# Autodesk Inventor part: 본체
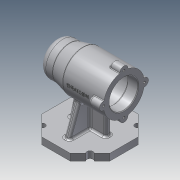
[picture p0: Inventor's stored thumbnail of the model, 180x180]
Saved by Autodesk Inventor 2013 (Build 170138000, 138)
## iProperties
Created: 2021-01
Part Number: 본체
Material: 알루미늄 6061
Document SubType Name: Modeling
Designer: user
Density: 2.71 g/cm^3
Mass: 632.297 g
Surface Area: 613.777 cm^2
Volume: 233.32 cm^3
Author: user
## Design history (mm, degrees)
sketch "스케치1"
  geometry: L1 (0, 0)-(-100, 0); L2 (-100, 0)-(-100, 25); L3 (0, 30)-(0, 0); L4 (0, 30)-(-60, 30); L5 (-60, 30)-(-80, 25); L6 (-80, 25)-(-100, 25); L7 (0, 21)-(-15, 21); L8 (-15, 21)-(-15, 24); L9 (-15, 24)-(-57, 24); L10 (-57, 24)-(-57, 21); L11 (-57, 21)-(-69, 21); L12 (-69, 21)-(-69, 17.5); L13 (-69, 17.5)-(-87, 17.5); L14 (-87, 17.5)-(-87, 16); L15 (-87, 16)-(-91, 16); L16 (-91, 16)-(-91, 10.5); L17 (-91, 10.5)-(-94, 10.5); L18 (-94, 10.5)-(-94, 0)
  constraints: 37 end point, 10 parallel, 5 perpendicular, 2 point on line, 1 collinear, 1 horizontal
  dimensions: "d1" = 60 diameter of L4 L1; "d3" = 48 diameter of L9 L1; "d4" = 42 diameter of L7 L1; "d5" = 15 distance between parallel lines of L3 L8; "d6" = 42 distance between parallel lines of L10 L8; "d7" = 12 distance between parallel lines of L10 L12; "d8" = 42 diameter of L11 L1; "d9" = 3 distance between parallel lines of L16 L18; "d10" = 4 distance between parallel lines of L14 L16; "d11" = 18 distance between parallel lines of L12 L14; "d12" = 100 distance of L1.start L1.end; "d13" = 40 distance from line of L2 L4.end; "d14" = 20 distance of L5.end L2.end; "d15" = 50 diameter of L6 L1; "d16" = 35 diameter of L13 L1; "d17" = 32 diameter of L15 L1; "d18" = 21 diameter of L17 L1
revolve "회전1" sketch "스케치1" stored, may be unused: angle "d19" = 90 deg
sketch "스케치2"
  geometry: C1 r 21 at (0, 0) reference; C2 r 6 at (0, 30); 1 further point
  constraints: 2 vertical alignment, 1 centre point, 1 other
  dimensions: "d20" = 12 diameter of C2
extrude "돌출1" join sketch "스케치2" distance "d22" = 16; taper "d23" = 0 deg
sketch "스케치3"
  geometry: A1 r 6 centre (0, 0) between (5.97, -0.6) and (-5.97, -0.6) reference; 1 further point
  constraints: 1 coincident
hole "구멍1" sketch "스케치3" at (0, 0) diameter "d24" = 3.242; stored, may be unused: countersink angle "d28" = 90 deg, drill point angle "d30" = 118 deg; dims "d25" = 8, "d26" = 4, "d27" = 2, "d29" = 10
node "작업 평면1"
sketch "스케치4"
  geometry: L1 (29.289, -50)-(0, -20.711); L2 (0, -20.711)-(0, 20.711); L3 (0, 20.711)-(29.289, 50); L4 (29.289, 50)-(70.711, 50); L5 (70.711, 50)-(100, 20.711); L6 (100, 20.711)-(100, -20.711); L7 (100, -20.711)-(70.711, -50); L8 (70.711, -50)-(29.289, -50); 3 further points
  constraints: 16 end point, 1 coincident, 1 horizontal alignment, 1 midpoint, 17 other
  dimensions: "d35" = 50 distance from line of L2 point (50, 0)
extrude "돌출2" join sketch "스케치4" distance "d36" = 10; taper "d37" = 0 deg
sketch "스케치5"
  geometry: L1 (-29.289, 50)-(-70.711, 50) reference; L2 (-70.711, 50)-(-100, 20.711) reference; L3 (-100, 20.711)-(-100, -20.711) reference; L4 (-70.711, -50)-(-29.289, -50) reference; L5 (-50, 50)-(-50, -50); L6 (-100, 0)-(0, 0); L7 (-50, 0)-(-85.355, 35.355); L8 (0, 20.711)-(-29.289, 50) reference; L9 (-100, -20.711)-(-70.711, -50) reference; L10 (-29.289, -50)-(0, -20.711) reference; C1 r 4.5 at (-85.355, 35.355); C2 r 4.5 at (-14.645, 35.355); C3 r 4.5 at (-14.645, -35.355); C4 r 4.5 at (-85.355, -35.355)
  constraints: 8 midpoint, 6 end point, 4 centre point, 2 perpendicular
  dimensions: "d38" = 9 diameter of C1; "d41" = 9 diameter of C2; "d42" = 9 diameter of C3; "d43" = 9 diameter of C4
extrude "돌출3" cut sketch "스케치5" stored distance "d39" = 10; taper "d40" = 0 deg
sketch "스케치6"
  geometry: L1 (0, -20.711)-(0, 20.711) reference; L2 (-100, 20.711)-(-100, -20.711) reference; L3 (-77, -4)-(-23, -4); L4 (-23, -4)-(-23, 4); L5 (-23, 4)-(-77, 4); L6 (-77, 4)-(-77, -4); L7 (-77, -4)-(-23, 4); L8 (-23, -4)-(-77, 4); 4 further points
  constraints: 12 end point, 4 midpoint, 2 parallel, 1 horizontal, 1 horizontal alignment, 1 perpendicular
  dimensions: "d44" = 8 distance of L3.end L4.end; "d46" = 50 distance from line of L1 point (-50, 0); "d47" = 23 distance between parallel lines of L2 L6
extrude "돌출4" join sketch "스케치6" stored distance "d48" = 10; taper "d49" = 0 deg
fillet "모깎기1" dims "d50" = 10
fillet "모깎기2" dims "d51" = 3
fillet "모깎기3" dims "d52" = 3
fillet "모깎기4" dims "d53" = 1
feature "면 기울기1" dims angle "d54" = 11 deg
node "작업 평면2"
sketch "스케치7"
  geometry: L1 (70.711, 0)-(-29.289, 0) reference; L2 (-29.289, 0)-(-29.289, 10) reference; L3 (-29.289, 10)-(16.711, 10) reference; L4 (16.711, 10)-(16.711, 45.268) reference; L5 (24.711, 45.268)-(24.711, 10) reference; L6 (24.711, 10)-(70.711, 10) reference; L7 (70.711, 10)-(70.711, 0) reference; L8 (1.104, 52.293)-(-14.289, 10); C1 r 24 at (20.711, 75) reference; A1 r 30 centre (20.711, 75) between (24.711, 45.268) and (16.711, 45.268) reference; 1 further point
  constraints: 2 end point, 1 point on circle, 1 point on line
  dimensions: "d56" = 15 distance from line of L8.end L2; "d57" = 110 deg angle of L3 L8
feature "리브1" sketch "스케치7" dims "d58" = 1, "d59" = 8, "d60" = 0, "d61" = 0, "d62" = 1, "d63" = 1
fillet "모깎기5" dims "d64" = 3
fillet "모깎기6" dims "d65" = 3
fillet "모깎기7" dims "d66" = 3
fillet "모깎기8" dims "d67" = 0.3, "d68" = 3
chamfer "모따기1" distance "d69" = 1; stored, may be unused: second distance "d70" = 2, angle "d71" = 45 deg
node "작업 평면3"
sketch "스케치8"
  geometry: L1 (0, 6.771)-(0, 29.226) reference; 2 further points
  constraints: 1 horizontal alignment, 1 other
  dimensions: "d73" = 38 distance from line of L1 point (-38, 0)
feature "엠보싱1" sketch "스케치8" dims "d74" = 0.5, "d75" = 0
node "솔리드1"
pattern_circular "원형 패턴1" dims angle "d32" = 360 deg
mirror "대칭1"
node "절단 모서리 투영1"
other parameters: "d34" = -75, "d72" = 69
